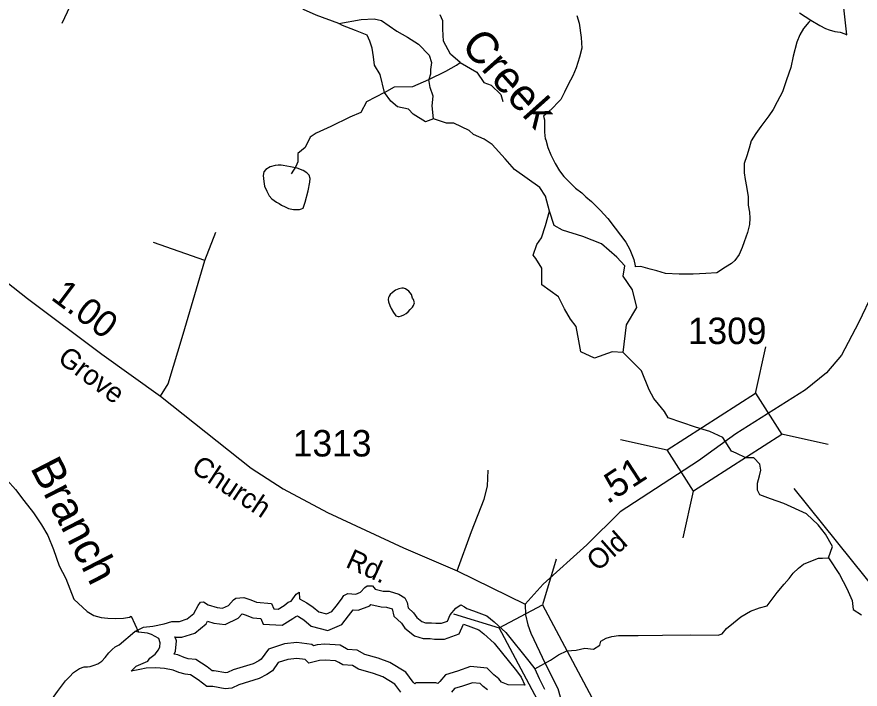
# Model space of a CAD drawing. Extents: x 2082433 to 2279600, y 546599 to 755198.
# Drawn here: x 2113702 to 2117688, y 630270 to 633447 of the extents above; entities that cross this region are included whole.
import ezdxf

# ---------------------------------------------------------------- set-up
doc = ezdxf.new("R2010")
doc.units = 0
for name, color, linetype in [('Exist Hydrographic Buffer Line', 7, 'Continuous'), ('Exist Hydrographic Creek Single Shore', 7, 'Continuous'), ('Exist Hydrographic Creek Single Shore Label', 7, 'Continuous'), ('Exist Hydrographic Lake Shore', 7, 'Continuous'), ('Exist Hydrographic Misc Water Feature', 7, 'Continuous'), ('Exist Road Non-System Type 51', 7, 'Continuous'), ('Exist Road Secondary Mileage Hundredths English Label', 7, 'Continuous'), ('Exist Road Secondary Structure Standard Bridge CELL', 7, 'Continuous'), ('Exist Road Secondary Structure Standard Bridge Number Label', 7, 'Continuous'), ('Exist Road Secondary Type 51 Attributed', 7, 'Continuous'), ('Exist Road Secondary Type 51 Label', 7, 'Continuous'), ('Exist Road Secondary Type 51 Number Label', 7, 'Continuous')]:
    doc.layers.add(name, color=color, linetype=linetype)

msp = doc.modelspace()

# ---------------------------------------------------------------- linework, layer by layer
at = {"layer": 'Exist Hydrographic Buffer Line'}
msp.add_lwpolyline([(2115793.1, 630532), (2115813.3, 630577), (2115834.9, 630569.1), (2115885.9, 630550.7), (2115909.9, 630531.5), (2115958.3, 630486.7), (2116063.6, 630356.8), (2116085.6, 630327.5), (2116103, 630289.2), (2116024.1, 630291.1), (2116016.1, 630294.4), (2115992.3, 630303.5), (2115980.8, 630318.6), (2115957.4, 630338.3), (2115925.9, 630369.8), (2115845.8, 630376.5), (2115785, 630355.4), (2115729, 630338.3), (2115701.6, 630306.9), (2115692.3, 630297.1), (2115682.8, 630299.6), (2115587.7, 630299.6), (2115582.7, 630294.7), (2115575.6, 630302.7), (2115540.1, 630350.9), (2115464.7, 630396.1), (2115410, 630416), (2115346.5, 630433.5), (2115311.1, 630455), (2115265.2, 630458.1), (2115260.6, 630460.7), (2115230.9, 630477.7), (2115158, 630482.2), (2115121.8, 630479.3), (2115104, 630475.3), (2115097.1, 630481.4), (2115026, 630490.8), (2114966.5, 630483.7), (2114890.8, 630459.6), (2114856.4, 630411.2), (2114845.4, 630403.8), (2114818.7, 630389.6), (2114724.6, 630361.3), (2114697.4, 630348.1), (2114690.1, 630347.4), (2114634.4, 630357), (2114625.6, 630357), (2114601.9, 630376), (2114548.1, 630409.8), (2114511.7, 630414.2), (2114492.7, 630419.6), (2114462.4, 630431.9), (2114445, 630435.5), (2114451.4, 630450.4), (2114456.4, 630497.9), (2114450.3, 630515.4), (2114447.7, 630515.4), (2114481.4, 630515.4), (2114543.5, 630534.4), (2114596.7, 630578.7), (2114603.8, 630591.6), (2114633.7, 630582.4), (2114686.2, 630575.8), (2114748.7, 630604.8), (2114767.6, 630626.3), (2114780.6, 630621.7), (2114817.7, 630606.6), (2114855.2, 630603.9), (2114866.9, 630577.3), (2114955.5, 630572.7), (2115006.9, 630603.8), (2115020.1, 630613.6), (2115028.2, 630616.5), (2115033.9, 630613.3), (2115058.3, 630597.8), (2115093.1, 630567.1), (2115172.6, 630547.3), (2115238.7, 630576.4), (2115270.3, 630616.2), (2115292.1, 630645), (2115315.4, 630643.7), (2115370.7, 630663.9), (2115375.8, 630669.8), (2115423.7, 630659.1), (2115449.8, 630658.2), (2115476.4, 630650.3), (2115483.6, 630614.4), (2115520.2, 630582.1), (2115535.6, 630557.9), (2115581.5, 630521.5), (2115623.3, 630509.2), (2115656.2, 630509.2), (2115676.6, 630506.2), (2115723.3, 630506.2)], close=True, dxfattribs=at)
at = {"layer": 'Exist Hydrographic Creek Single Shore'}
for points in [[(2115223.3, 633415.5), (2115116.7, 633454.5), (2115057.3, 633481.1), (2115040.9, 633509.8), (2115034.7, 633544.6), (2115034.7, 633606.1), (2115034.7, 633667.6), (2115034.7, 633725), (2115034.7, 633786.4), (2115028.6, 633837.6), (2115018.3, 633870.4), (2114995.8, 633893), (2114954.8, 633909.4), (2114924.3, 633923.8)], [(2113952.8, 633495.5), (2113913.9, 633415.5)], [(2115797, 633231.1), (2115751.9, 633270.1), (2115719.1, 633331.5), (2115715, 633388.9), (2115715, 633427.8), (2115702.7, 633456.5)], [(2115223.3, 633415.5), (2115329.8, 633434), (2115391.3, 633438.1), (2115426.1, 633429.9), (2115497.8, 633378.7), (2115549.1, 633350), (2115600.3, 633317.2), (2115651.5, 633266), (2115661.8, 633231.1), (2115657.7, 633198.3), (2115657.7, 633175.8), (2115649.5, 633151.2)], [(2115440.5, 633089.7), (2115420, 633173.8), (2115393.3, 633218.8), (2115387.2, 633257.8), (2115381, 633298.7), (2115370.8, 633331.5), (2115358.5, 633360.2), (2115303.2, 633382.8), (2115241.7, 633405.3), (2115223.3, 633415.5)], [(2115649.5, 633151.2), (2115729.4, 633190.1), (2115780.6, 633218.8), (2115797, 633231.1)], [(2115797, 633231.1), (2115876.9, 633186), (2115909.7, 633136.9), (2115944.5, 633124.6), (2115989.6, 633079.5), (2115999.8, 633046.7)], [(2115440.5, 633089.7), (2115487.6, 633116.4), (2115573.6, 633118.4), (2115649.5, 633151.2)], [(2115672, 632964.7), (2115665.8, 633026.2), (2115669.9, 633071.3), (2115655.6, 633112.3), (2115649.5, 633151.2)], [(2115440.5, 633089.7), (2115354.4, 633044.7), (2115327.8, 632995.5), (2115276.5, 632972.9), (2115186.4, 632927.9), (2115116.7, 632897.1), (2115088, 632878.7), (2115065.5, 632829.5), (2115030.6, 632800.8), (2115030.6, 632761.9), (2115020.4, 632739.3), (2114997.9, 632704.5)], [(2115672, 632964.7), (2115633.1, 632950.4), (2115575.7, 632987.3), (2115553.2, 633009.8), (2115501.9, 633022.1), (2115469.1, 633048.8), (2115440.5, 633089.7)], [(2115840, 632909.4), (2115768.3, 632944.3), (2115733.5, 632944.3), (2115704.8, 632954.5), (2115672, 632964.7)], [(2116219.1, 632528.3), (2116200.7, 632600), (2116174, 632641), (2116055.2, 632725), (2116010.1, 632776.2), (2115948.6, 632843.9), (2115911.7, 632868.4), (2115860.5, 632891), (2115840, 632909.4)], [(2116143.3, 632321.3), (2116159.7, 632370.5), (2116182.2, 632403.3), (2116200.7, 632460.7), (2116219.1, 632528.3)], [(2116567.4, 631860.3), (2116583.8, 631991.4), (2116633, 632073.4), (2116612.5, 632157.4), (2116567.4, 632220.9), (2116575.6, 632270.1), (2116538.8, 632311.1), (2116465, 632374.6), (2116376.9, 632409.4), (2116280.6, 632438.1), (2116241.6, 632460.7), (2116219.1, 632528.3)], [(2116516.2, 631864.4), (2116432.2, 631833.7), (2116368.7, 631864.4), (2116358.4, 631915.6), (2116346.1, 631983.2), (2116319.5, 632018.1), (2116290.8, 632067.3), (2116262.1, 632124.6), (2116184.3, 632180), (2116184.3, 632259.9), (2116155.6, 632304.9), (2116143.3, 632321.3)], [(2111711.6, 631907.2), (2113174.2, 631425.4), (2113655.5, 631257.5), (2113695.9, 631213.7), (2113734.1, 631161.6), (2113780, 631104), (2113818.6, 631046.2), (2113848.9, 630996.3), (2113874.8, 630930.3), (2113901.4, 630852.4), (2113933.6, 630792.8), (2113971.9, 630694.9), (2114034.3, 630637.2), (2114066.3, 630617.4), (2114100.1, 630609.4), (2114132.3, 630605.8), (2114168.2, 630604), (2114206.3, 630606), (2114234.2, 630610.2), (2114242.2, 630614.3), (2114276.6, 630540.2)], [(2117538.2, 630891.1), (2117557.1, 630944.4), (2117524.4, 631001.7), (2117489.5, 631046.8), (2117434.2, 631098), (2117327.6, 631147.2), (2117264.1, 631169.8), (2117214.9, 631188.2), (2117202.6, 631210.7), (2117202.6, 631243.5), (2117212.9, 631278.4), (2117219, 631305), (2117214.9, 631333.7), (2117186.3, 631362.4), (2117147.3, 631362.4), (2117102.2, 631384.9), (2117079.7, 631395.2), (2117038.7, 631458.7), (2116977.3, 631487.4), (2116909.6, 631507.9), (2116780.5, 631552.9), (2116764.1, 631581.6), (2116735.5, 631616.5), (2116712.9, 631643.1), (2116690.4, 631684.1), (2116655.5, 631774.2), (2116567.4, 631860.3), (2116516.2, 631864.4)], [(2116150.5, 630366), (2116224.7, 630406.5), (2116262.6, 630431.6), (2116302.1, 630451.6), (2116345.6, 630454.1), (2116387.6, 630464.4), (2116427.6, 630459.8), (2116457.3, 630478.2), (2116461.9, 630496.6), (2116488, 630510.5), (2116514.7, 630518.7), (2116545.9, 630523.3), (2116587.9, 630524.3), (2116638.6, 630523.3), (2116754.4, 630525.8), (2116884.5, 630526.9), (2117017.2, 630524.8), (2117036.7, 630531.5), (2117056.1, 630556.1), (2117090, 630583.2), (2117123.8, 630612.4), (2117169.4, 630638), (2117212.9, 630654.9), (2117249.3, 630663.1), (2117268.2, 630688.7), (2117296.4, 630726.7), (2117329.7, 630766.1), (2117352.2, 630792.7), (2117372.2, 630817.8), (2117396.3, 630841.9), (2117421.4, 630860.4), (2117447, 630871.6), (2117492.1, 630888.5), (2117510, 630888.5), (2117538.2, 630891.1), (2117590.9, 630812.2), (2117624.8, 630745.6), (2117650.4, 630689.3), (2117655.5, 630646.2), (2117695.4, 630620.6)], [(2113722.4, 630110.2), (2113752.3, 630124.3), (2113772.2, 630136.3), (2113796.2, 630150.5), (2113814.3, 630168.5), (2113840.1, 630194.6), (2113870.2, 630226.5), (2113893.8, 630258.6), (2113932, 630308.8), (2113951.4, 630329), (2113969.7, 630348.9), (2113997.8, 630367), (2114019.5, 630375.1), (2114035.3, 630375.5), (2114049.2, 630377.5), (2114067.3, 630383.6), (2114085.1, 630389.5), (2114103.4, 630401.7), (2114119.2, 630419.6), (2114136.8, 630441.7), (2114153.2, 630457.9), (2114166.9, 630469.9), (2114184.8, 630479.8), (2114260.2, 630543.3)]]:
    msp.add_lwpolyline(points, dxfattribs=at)
at = {"layer": 'Exist Hydrographic Lake Shore'}
for points in [[(2115517.3, 630255.4), (2115488.6, 630294.3), (2115432.3, 630328.1), (2115387.2, 630344.5), (2115316.5, 630364), (2115287.8, 630381.4), (2115242.7, 630384.5), (2115223.3, 630395.7), (2115208.9, 630403.9), (2115158.7, 630407), (2115133.1, 630404.9), (2115082.9, 630393.7), (2115064.4, 630410.1), (2115025.5, 630415.2), (2114982.5, 630410.1), (2114937.4, 630395.7), (2114909.7, 630356.8), (2114884.1, 630339.4), (2114847.2, 630319.9), (2114752, 630291.2), (2114718.2, 630274.8), (2114687.4, 630271.8), (2114628, 630282), (2114599.3, 630282), (2114558.3, 630314.8), (2114522.5, 630337.3), (2114496.9, 630340.4), (2114468.2, 630348.6), (2114440.5, 630359.9), (2114400.6, 630368.1), (2114358.5, 630371.1), (2114313.5, 630369.1), (2114282.7, 630362.9), (2114242.8, 630354.7), (2114265.3, 630379.3), (2114321.7, 630401.9), (2114329.9, 630416.2), (2114355.5, 630435.7), (2114371.9, 630455.2), (2114378, 630469.5), (2114380.1, 630489), (2114372.9, 630509.5), (2114339.1, 630528.9), (2114319.6, 630534), (2114276.6, 630540.2), (2114260.2, 630543.3), (2114301.2, 630562.7), (2114344.2, 630567.9), (2114397.5, 630579.1), (2114434.4, 630590.4), (2114447.7, 630590.4), (2114470.2, 630590.4), (2114507.1, 630601.7), (2114537.8, 630627.3), (2114559.4, 630666.2), (2114570.6, 630680.5), (2114583.9, 630682.6), (2114606.5, 630669.3), (2114649.5, 630656), (2114674.1, 630652.9), (2114702.8, 630666.2), (2114725.3, 630691.8), (2114736.6, 630700), (2114775.5, 630703.1), (2114807.3, 630691.8), (2114835, 630680.5), (2114905.6, 630675.4), (2114916.9, 630649.8), (2114936.4, 630648.8), (2114965.1, 630666.2), (2114984.5, 630680.5), (2114998.9, 630685.7), (2115022.4, 630719.5), (2115035.8, 630727.7), (2115038.8, 630696.9), (2115072.6, 630677.5), (2115103.4, 630658), (2115129, 630635.5), (2115165.9, 630626.2), (2115191.5, 630637.5), (2115211, 630662.1), (2115236.6, 630695.9), (2115247.8, 630713.3), (2115267.3, 630721.5), (2115304.2, 630719.5), (2115326.7, 630727.7), (2115346.2, 630750.2), (2115357.5, 630758.4), (2115383.1, 630758.4), (2115396.4, 630742), (2115433.3, 630733.8), (2115462, 630732.8), (2115507, 630719.5), (2115535.7, 630702.1), (2115547, 630679.5), (2115552.1, 630653.9), (2115577.7, 630631.4), (2115592.1, 630608.8), (2115616.7, 630589.4), (2115634.1, 630584.2), (2115661.8, 630584.2), (2115682.2, 630581.2), (2115709.9, 630581.2), (2115737.6, 630591.4), (2115750.9, 630621.1), (2115776.5, 630652.9), (2115792.9, 630664.2), (2115801.1, 630669.3), (2115818.5, 630659), (2115829.8, 630650.8), (2115860.5, 630639.6), (2115923, 630617), (2115958.9, 630588.3), (2116013.2, 630538.1), (2116122.8, 630402.9), (2116150.5, 630366), (2116170.9, 630320.9), (2116195.5, 630269.7)], [(2115926.1, 630266.6), (2115906.6, 630283), (2115892.3, 630297.4), (2115855.4, 630300.4), (2115808.3, 630284.1), (2115771.4, 630272.8), (2115757, 630256.4)]]:
    msp.add_lwpolyline(points, dxfattribs=at)
at = {"layer": 'Exist Hydrographic Misc Water Feature'}
for points in [[(2117455.2, 633431.3), (2117497.2, 633405.5), (2117525.1, 633391.5), (2117541.3, 633385.8), (2117569.2, 633377.9), (2117593.2, 633373.9), (2117615.3, 633366.1), (2117625.2, 633362.2), (2117610.8, 633490.1)], [(2116349.5, 633452.7), (2116359.6, 633416.7), (2116369.8, 633348.6), (2116372.3, 633298.7), (2116362.2, 633256.5), (2116346.2, 633206.6), (2116330.5, 633168.4), (2116308.7, 633126.7), (2116291.3, 633090.4), (2116273.2, 633056.2), (2116258.9, 633042.5), (2116235.5, 633016.1), (2116213.4, 632995.9), (2116191.6, 632978.1)], [(2117401, 633465.1), (2117455.2, 633431.3)], [(2117455.2, 633431.3), (2117445.1, 633421.5), (2117421.3, 633391.4), (2117403.7, 633361.2), (2117389.5, 633327.3), (2117372.1, 633261), (2117360, 633206.8), (2117340.1, 633149), (2117320.7, 633092.8), (2117296.9, 633044.8), (2117276.8, 633008.5), (2117257.1, 632978.7), (2117219.4, 632928.4), (2117195.6, 632896.3), (2117173.8, 632860.2), (2117163.6, 632826.2), (2117152.1, 632790.2), (2117140.6, 632754.2), (2117140.4, 632710), (2117144.5, 632678.2), (2117150.7, 632644.4), (2117158.9, 632596.5), (2117159.1, 632556.3), (2117165, 632524.2), (2117167.3, 632496.3), (2117165.2, 632466.1), (2117155.6, 632428.3), (2117139.6, 632384.1), (2117130, 632356.3), (2117116, 632324.3), (2117096.1, 632296.1), (2117080.1, 632281.9), (2117052.4, 632263.8), (2117010.6, 632237.7), (2116958.5, 632233.4), (2116898.7, 632231.1), (2116832.8, 632230.9), (2116768.7, 632234.6), (2116726.6, 632246.6), (2116696.5, 632254.4), (2116652.4, 632266.4), (2116624.3, 632266.2)], [(2116191.6, 632978.1), (2116195.5, 632960.1), (2116195.5, 632932.1), (2116195.5, 632902.1), (2116200, 632870.2), (2116201.9, 632866.2)], [(2116201.9, 632866.2), (2116212.1, 632830.2), (2116226.1, 632794.1), (2116246.6, 632754.4), (2116266.7, 632718.6), (2116287, 632692.4), (2116312.8, 632666.6), (2116342.8, 632636.9), (2116373.1, 632614.8), (2116391.4, 632597.1), (2116419, 632575), (2116459.4, 632533.2), (2116495.5, 632493.3), (2116529.6, 632447.6), (2116580, 632382), (2116600.1, 632348.1), (2116618.6, 632299.9), (2116624.7, 632270.2), (2116624.3, 632266.2)], [(2114950.7, 632746.6), (2114936.7, 632746.7), (2114922.8, 632744.7), (2114898.8, 632738.6), (2114879.3, 632726.2), (2114869.3, 632714.3), (2114867, 632696.4), (2114869.3, 632668.5), (2114873.1, 632646.4), (2114883.2, 632622.5), (2114895.3, 632600.4), (2114907.4, 632586.4), (2114917.6, 632578.4), (2114929.3, 632570.6), (2114941.6, 632564.7), (2114953.5, 632556.8), (2114969.5, 632548.7), (2114985.7, 632540.9), (2115009.7, 632536.9), (2115037.8, 632537.1), (2115047.9, 632539.2), (2115055.9, 632543.3), (2115065.5, 632571), (2115079.2, 632625.4), (2115087.2, 632665.1), (2115088.9, 632683.5), (2115083.1, 632699.4), (2115073.3, 632709), (2115054.8, 632721.1), (2115026.7, 632731), (2114994.7, 632738.7), (2114960.5, 632744.7), (2114950.7, 632746.6)], [(2115573, 632117.4), (2115567.3, 632135.4), (2115555.4, 632151.3), (2115539.2, 632161.5), (2115529.3, 632165.4), (2115521.1, 632165.4), (2115507.2, 632161.1), (2115491.4, 632155.3), (2115477.4, 632144.9), (2115467.2, 632135.1), (2115461.2, 632127.1), (2115459.4, 632120.9), (2115457.8, 632111), (2115459.4, 632101), (2115465.3, 632083), (2115471.5, 632069.2), (2115481.7, 632049.3), (2115489.9, 632039.2), (2115494, 632033.3), (2115503.9, 632031.4), (2115509.8, 632031.3), (2115519.9, 632033.4), (2115531.6, 632039.4), (2115542, 632045.5), (2115551.5, 632053.4), (2115561.5, 632063.6), (2115571.6, 632075.5), (2115577.7, 632083.5), (2115581.8, 632095.4), (2115577.3, 632111.5), (2115573, 632117.4)]]:
    msp.add_lwpolyline(points, dxfattribs=at)
at = {"layer": 'Exist Road Non-System Type 51'}
for q in [(2114642.8, 632429.1), (2114347.1, 632380.4)]:
    msp.add_line((2114591, 632295), q, dxfattribs=at)
for points in [[(2114380.6, 631654.6), (2114417.2, 631712.6), (2114487.3, 631947.4), (2114591, 632295)], [(2115783.3, 630829.8), (2115850.4, 631015.8), (2115911.3, 631168.3), (2115926.6, 631229.3), (2115929.6, 631305.5)]]:
    msp.add_lwpolyline(points, dxfattribs=at)
at = {"layer": 'Exist Road Secondary Structure Standard Bridge CELL'}
for p, q in [((2117194.3, 631667), (2117242.8, 631888.1)), ((2117316.2, 631476.4), (2117537.3, 631427.8)), ((2116555, 631449.4), (2116776.1, 631400.8)), ((2116852.3, 630984.6), (2116900.9, 631205.7)), ((2116252.1, 630885.1), (2116186.2, 630668.5)), ((2115765.3, 630625.5), (2115981.8, 630559.6))]:
    msp.add_line(p, q, dxfattribs=at)
for points in [[(2116776.1, 631400.8), (2117193.7, 631667.9), (2117318.5, 631472.9), (2116900.9, 631205.7)], [(2116186.2, 630668.5), (2116419.4, 630231), (2116215, 630122.1), (2115981.8, 630559.6)]]:
    msp.add_lwpolyline(points, close=True, dxfattribs=at)
at = {"layer": 'Exist Road Secondary Structure Standard Bridge Number Label'}
msp.add_line((2117375.3, 631217.5), (2118613.2, 629673.9), dxfattribs=at)
at = {"layer": 'Exist Road Secondary Type 51 Attributed'}
for points in [[(2111652.7, 633416.1), (2111894.5, 633322.9), (2112079.1, 633250.5), (2112268.5, 633172.4), (2112497.6, 633053), (2112667.1, 632954.3), (2112932.8, 632752.1), (2113270.1, 632495.7), (2113751.5, 632116.7), (2114103.2, 631852.4), (2114380.6, 631654.6), (2114808.9, 631314.2), (2114961.6, 631217), (2115170.9, 631105.6), (2115528.9, 630938.4), (2115783.3, 630829.8), (2116104.5, 630672.4)], [(2117918.3, 632556.3), (2117891.3, 632465.6), (2117815.7, 632284), (2117680.5, 632000.6), (2117600.9, 631847.7), (2117530.1, 631764.9), (2117429.8, 631683.7), (2117101.3, 631477.2)], [(2117101.3, 631477.2), (2116923.7, 631348.2), (2116554.7, 631107.3), (2116396.2, 630951.8), (2116190.2, 630766.5), (2116104.5, 630672.4)], [(2116104.5, 630672.4), (2116106.4, 630621.1), (2116117.7, 630574), (2116131, 630535.1), (2116199.6, 630391.6)], [(2116199.6, 630391.6), (2116259.1, 630272.8), (2116344.1, 629969.5), (2116469.4, 629611.6), (2116551.7, 629288.4), (2116566.9, 629203), (2116588.3, 628992.6), (2116600.5, 628753.3), (2116600.5, 628670.9), (2116658.4, 628048.9), (2116693.5, 627758.4), (2116707.7, 627475.4)]]:
    msp.add_lwpolyline(points, dxfattribs=at)

# ---------------------------------------------------------------- texts
at = {"layer": 'Exist Hydrographic Creek Single Shore Label'}
for s, rotation, p in [('Creek', 311.7409, (2115796.5, 633307.7)), ('Branch', 297.3347, (2113763.2, 631316.3))]:
    msp.add_text(s, height=150, rotation=rotation, dxfattribs=at).set_placement(p)
at = {"layer": 'Exist Road Secondary Mileage Hundredths English Label'}
for s, rotation, p in [('1.00', 323.0692, (2113857.7, 632115)), ('.51', 33.1402, (2116493.8, 631142.2))]:
    msp.add_text(s, height=125, rotation=rotation, dxfattribs=at).set_placement(p)
at = {"layer": 'Exist Road Secondary Type 51 Label'}
for s, rotation, p in [('Grove', 323.0909, (2113889.1, 631821)), ('Church', 326.4335, (2114520.7, 631301.7)), ('Old', 41.4998, (2116447.7, 630823)), ('Rd.', 335.4111, (2115251.2, 630849.2))]:
    msp.add_text(s, height=95, rotation=rotation, dxfattribs=at).set_placement(p)
at = {"layer": 'Exist Road Secondary Type 51 Number Label'}
for s, p in [('1309', (2116873.7, 631900.7)), ('1313', (2115006.4, 631369.5))]:
    msp.add_text(s, height=125, dxfattribs=at).set_placement(p)

doc.saveas('drawing.dxf')
